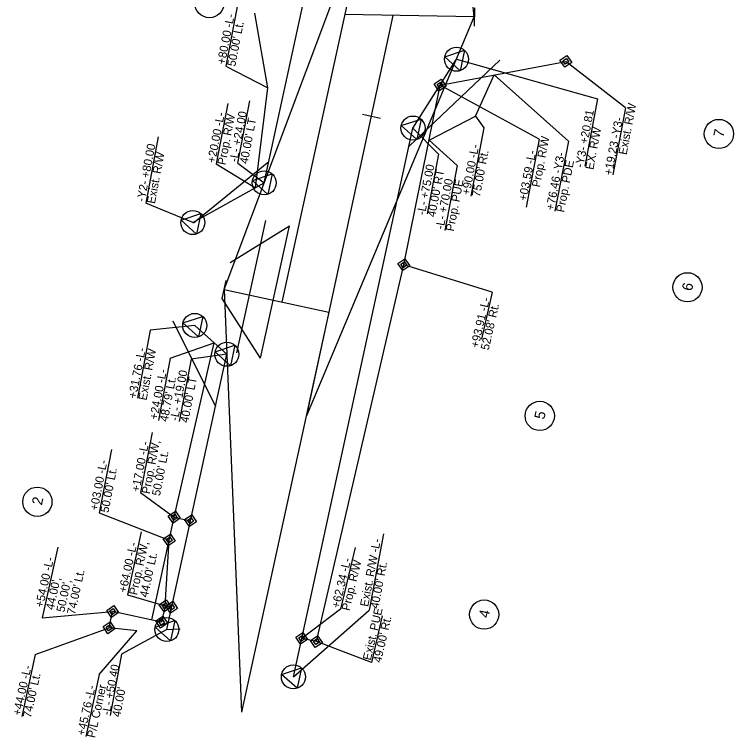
# Model space of a CAD drawing. Extents: x 1610947 to 1617684, y 899814 to 904658.
# Drawn here: x 1616111.3 to 1616541.5, y 899813.7 to 900246.6 of the extents above; entities that cross this region are included whole.
import ezdxf

# ---------------------------------------------------------------- set-up
doc = ezdxf.new("R2010")
doc.units = 0
for name, color, linetype in [('Prop Conc 1ft 6in Curb and Gutter', 7, 'Continuous'), ('Prop Conc Valley Gutter', 7, 'Continuous'), ('Prop EOT Dash', 7, 'Continuous'), ('Prop Hatching', 7, 'Continuous'), ('Prop Horizontal Alignment Direction Label', 7, 'Continuous'), ('Prop Horizontal Alignment Tick Label', 7, 'Continuous'), ('Prop ROW Marker CELL', 7, 'Continuous'), ('Prop ROW RW Lines', 7, 'Continuous'), ('Prop ROW Station Offsets', 7, 'Continuous'), ('Scratch_Level_2', 7, 'Continuous'), ('Scratch_Level_3', 7, 'Continuous'), ('Scratch_Level_8', 7, 'Continuous'), ('Typical Terminator CELL', 7, 'Continuous')]:
    doc.layers.add(name, color=color, linetype=linetype)

msp = doc.modelspace()

# ---------------------------------------------------------------- linework, layer by layer
at = {"layer": 'Prop Conc 1ft 6in Curb and Gutter'}
for p, q in [((1616244.83, 900252.28), (1616237.75, 900215.63)), ((1616237.75, 900215.63), (1616262.86, 900202.61)), ((1616238.96, 900193.29), (1616232, 900157.23)), ((1616387.13, 900185.77), (1616392.22, 900178.8)), ((1616392.22, 900178.8), (1616384.45, 900137.85)), ((1616359.33, 900171.36), (1616376.19, 900156.16)), ((1616442.71, 900170.81), (1616434.62, 900128.9)), ((1616232, 900157.23), (1616255.43, 900142.82)), ((1616376.19, 900156.16), (1616368.8, 900117.25))]:
    msp.add_line(p, q, dxfattribs=at)
msp.add_lwpolyline([(1616442.71, 900170.81), (1616398.24, 900210.39)], dxfattribs=at)
at = {"layer": 'Prop Conc Valley Gutter'}
for p, q in [((1616347.37, 900167.7), (1616401.7, 900219.28)), ((1616218.41, 900121.92), (1616263.49, 900158.5)), ((1616206.14, 900063.18), (1616231.56, 900011.94))]:
    msp.add_line(p, q, dxfattribs=at)
at = {"layer": 'Prop EOT Dash'}
for points in [[(1616437.65, 900219.18), (1616441.86, 900222.05), (1616444.72, 900217.84), (1616440.51, 900214.98)], [(1616439.42, 900218.85), (1616441.52, 900220.28), (1616442.95, 900218.18), (1616440.85, 900216.74)], [(1616362.43, 900204.96), (1616366.64, 900207.83), (1616369.5, 900203.62), (1616365.3, 900200.75)], [(1616364.2, 900204.62), (1616366.3, 900206.06), (1616367.74, 900203.95), (1616365.63, 900202.52)], [(1616340.74, 900097.44), (1616344.95, 900100.31), (1616347.82, 900096.1), (1616343.61, 900093.23)], [(1616342.51, 900097.11), (1616344.61, 900098.54), (1616346.05, 900096.43), (1616343.94, 900095)], [(1616203.34, 899946.31), (1616207.55, 899949.18), (1616210.42, 899944.97), (1616206.21, 899942.1)], [(1616205.11, 899945.97), (1616207.22, 899947.41), (1616208.65, 899945.3), (1616206.55, 899943.87)], [(1616213.12, 899944.18), (1616217.32, 899947.05), (1616220.19, 899942.84), (1616215.98, 899939.97)], [(1616214.88, 899943.85), (1616216.99, 899945.28), (1616218.42, 899943.17), (1616216.32, 899941.74)], [(1616200.36, 899932.63), (1616204.57, 899935.5), (1616207.44, 899931.29), (1616203.23, 899928.42)], [(1616202.13, 899932.3), (1616204.24, 899933.73), (1616205.67, 899931.62), (1616203.57, 899930.19)], [(1616197.93, 899893.25), (1616202.13, 899896.11), (1616205, 899891.9), (1616200.79, 899889.04)], [(1616199.69, 899892.91), (1616201.8, 899894.34), (1616203.23, 899892.24), (1616201.13, 899890.81)], [(1616201.83, 899892.4), (1616206.04, 899895.26), (1616208.91, 899891.05), (1616204.7, 899888.19)], [(1616203.6, 899892.06), (1616205.71, 899893.49), (1616207.14, 899891.39), (1616205.03, 899889.96)], [(1616166.48, 899889.86), (1616170.69, 899892.73), (1616173.56, 899888.52), (1616169.35, 899885.65)], [(1616168.25, 899889.53), (1616170.36, 899890.96), (1616171.79, 899888.86), (1616169.69, 899887.42)], [(1616195.8, 899883.48), (1616200.01, 899886.34), (1616202.87, 899882.13), (1616198.66, 899879.27)], [(1616197.57, 899883.14), (1616199.67, 899884.57), (1616201.1, 899882.47), (1616199, 899881.04)], [(1616164.36, 899880.09), (1616168.56, 899882.96), (1616171.43, 899878.75), (1616167.22, 899875.88)], [(1616166.12, 899879.76), (1616168.23, 899881.19), (1616169.66, 899879.08), (1616167.56, 899877.65)], [(1616279.65, 899873.74), (1616283.85, 899876.61), (1616286.72, 899872.4), (1616282.51, 899869.53)], [(1616281.41, 899873.4), (1616283.52, 899874.84), (1616284.95, 899872.73), (1616282.85, 899871.3)], [(1616288.44, 899871.82), (1616292.65, 899874.69), (1616295.51, 899870.48), (1616291.3, 899867.62)], [(1616290.21, 899871.49), (1616292.31, 899872.92), (1616293.74, 899870.82), (1616291.64, 899869.38)]]:
    msp.add_lwpolyline(points, close=True, dxfattribs=at)
at = {"layer": 'Prop Hatching'}
for centre in [(1616227.92, 900253.37), (1616532.79, 900175.04), (1616513.98, 900083.25), (1616425.61, 900006.24), (1616124.98, 899954.88), (1616392.33, 899887.32)]:
    msp.add_circle(centre, 8.75, dxfattribs=at)
at = {"layer": 'Prop Horizontal Alignment Direction Label'}
for p, q in [((1616344.28, 900096.77), (1616365.97, 900204.29)), ((1616291.98, 899871.15), (1616344.28, 900096.77)), ((1616167.89, 899879.42), (1616170.02, 899889.19)), ((1616199.33, 899882.81), (1616170.02, 899889.19)), ((1616201.46, 899892.58), (1616199.33, 899882.81)), ((1616205.37, 899891.72), (1616201.46, 899892.58)), ((1616184.59, 899877.59), (1616167.89, 899879.42)), ((1616291.98, 899871.15), (1616283.18, 899873.07))]:
    msp.add_line(p, q, dxfattribs=at)
at = {"layer": 'Prop Horizontal Alignment Tick Label'}
for p, q in [((1616397.19, 900080.35), (1616344.28, 900096.77)), ((1616397.19, 900080.35), (1616390.74, 900052.27)), ((1616187.09, 899936.95), (1616178.86, 899899.23)), ((1616137.18, 899927.69), (1616127.93, 899885.32)), ((1616315.11, 899927.48), (1616306.31, 899890.59)), ((1616127.93, 899885.32), (1616170.02, 899889.19)), ((1616331.27, 899886.64), (1616324.82, 899858.57)), ((1616324.82, 899858.57), (1616291.98, 899871.15)), ((1616123.72, 899863.42), (1616115.63, 899826.37)), ((1616162.02, 899851.42), (1616153.94, 899814.38))]:
    msp.add_line(p, q, dxfattribs=at)
for points in [[(1616178.86, 899899.23), (1616201.46, 899892.58)], [(1616306.31, 899890.59), (1616283.18, 899873.07)], [(1616123.72, 899863.42), (1616167.89, 899879.42)], [(1616162.02, 899851.42), (1616184.59, 899877.59)]]:
    msp.add_lwpolyline(points, dxfattribs=at)
at = {"layer": 'Prop ROW Marker CELL'}
for p, q in [((1616375.75, 900219.79), (1616375.75, 900219.79)), ((1616441.18, 900218.51), (1616441.18, 900218.51)), ((1616365.97, 900204.29), (1616365.97, 900204.29)), ((1616349.74, 900178.57), (1616349.74, 900178.57)), ((1616260.71, 900145.77), (1616260.71, 900145.77)), ((1616218.01, 900122), (1616218.01, 900122)), ((1616344.28, 900096.77), (1616344.28, 900096.77)), ((1616219.16, 900060.42), (1616219.16, 900060.42)), ((1616238.36, 900043.17), (1616238.36, 900043.17)), ((1616206.88, 899945.64), (1616206.88, 899945.64)), ((1616216.65, 899943.51), (1616216.65, 899943.51)), ((1616203.9, 899931.96), (1616203.9, 899931.96)), ((1616170.02, 899889.19), (1616170.02, 899889.19)), ((1616201.46, 899892.58), (1616201.46, 899892.58)), ((1616205.37, 899891.72), (1616205.37, 899891.72)), ((1616199.33, 899882.81), (1616199.33, 899882.81)), ((1616167.89, 899879.42), (1616167.89, 899879.42)), ((1616202.46, 899878.37), (1616202.46, 899878.37)), ((1616283.18, 899873.07), (1616283.18, 899873.07)), ((1616291.98, 899871.15), (1616291.98, 899871.15)), ((1616278.17, 899850.04), (1616278.17, 899850.04))]:
    msp.add_line(p, q, dxfattribs=at)
for points in [[(1616377.97, 900212.92), (1616368.7, 900221.28), (1616380.57, 900225.15)], [(1616351.96, 900171.71), (1616342.69, 900180.06), (1616354.56, 900183.93)], [(1616262.94, 900138.9), (1616253.67, 900147.26), (1616265.53, 900151.13)], [(1616220.23, 900115.14), (1616210.96, 900123.5), (1616222.83, 900127.37)], [(1616221.39, 900053.56), (1616212.12, 900061.91), (1616223.98, 900065.78)], [(1616240.59, 900036.31), (1616231.32, 900044.67), (1616243.18, 900048.54)], [(1616204.68, 899871.51), (1616195.42, 899879.87), (1616207.28, 899883.74)], [(1616280.39, 899843.18), (1616271.12, 899851.54), (1616282.99, 899855.41)]]:
    msp.add_lwpolyline(points, close=True, dxfattribs=at)
for centre in [(1616375.75, 900219.79), (1616349.74, 900178.57), (1616260.71, 900145.77), (1616218.01, 900122), (1616219.16, 900060.42), (1616238.36, 900043.17), (1616202.46, 899878.37), (1616278.17, 899850.04)]:
    msp.add_circle(centre, 7.2, dxfattribs=at)
at = {"layer": 'Prop ROW RW Lines'}
for p, q in [((1616260.71, 900145.77), (1616369.28, 900644.08)), ((1616349.74, 900178.57), (1616375.75, 900219.79)), ((1616278.17, 899850.04), (1616349.74, 900178.57)), ((1616218.01, 900122), (1616260.71, 900145.77)), ((1616238.36, 900043.17), (1616219.16, 900060.42)), ((1616202.46, 899878.37), (1616238.36, 900043.17)), ((1616202.46, 899878.37), (1616210.42, 899878.72))]:
    msp.add_line(p, q, dxfattribs=at)
at = {"layer": 'Prop ROW Station Offsets'}
for p, q in [((1616375.75, 900219.79), (1616460.13, 900196.06)), ((1616460.13, 900196.06), (1616452.47, 900155.71)), ((1616349.74, 900178.57), (1616365.01, 900162.99)), ((1616197.33, 900173.25), (1616189.82, 900133.68)), ((1616365.01, 900162.99), (1616358.21, 900127.17)), ((1616244.95, 900157.47), (1616260.71, 900145.77)), ((1616218.01, 900122), (1616189.82, 900133.68)), ((1616192.55, 900057.65), (1616184.81, 900016.87)), ((1616219.16, 900060.42), (1616192.55, 900057.65)), ((1616216.93, 900040.17), (1616209.77, 900002.82)), ((1616238.36, 900043.17), (1616216.93, 900040.17)), ((1616332.17, 899935.73), (1616323.5, 899890.03)), ((1616278.17, 899850.04), (1616323.5, 899890.03)), ((1616202.46, 899878.37), (1616175.42, 899863.63)), ((1616175.42, 899863.63), (1616168.46, 899826.99))]:
    msp.add_line(p, q, dxfattribs=at)
msp.add_lwpolyline([(1616244.95, 900157.47), (1616252.06, 900194.9)], dxfattribs=at)
at = {"layer": 'Scratch_Level_2'}
for p, q in [((1616386.37, 900245.08), (1616361.19, 900485.97)), ((1616236.81, 900081.92), (1616323.66, 900313.74)), ((1616271.51, 900074.36), (1616323.66, 900313.74)), ((1616386.47, 900250.58), (1616386.26, 900239.59)), ((1616286.24, 900006.55), (1616337.97, 900246.03)), ((1616286.24, 900006.55), (1616386.37, 900245.08)), ((1616386.37, 900245.08), (1616309.03, 900246.59)), ((1616319.55, 900186.82), (1616330.3, 900184.48)), ((1616244.41, 900043.93), (1616261.66, 900123.16)), ((1616240.35, 900098.03), (1616275.83, 900120.07)), ((1616258.58, 900040.84), (1616275.83, 900120.07)), ((1616235.64, 900076.54), (1616237.98, 900087.29)), ((1616236.81, 900081.92), (1616299.36, 900068.29)), ((1616236.81, 900081.92), (1616247.21, 899828.91)), ((1616258.58, 900040.84), (1616235.64, 900076.54)), ((1616299.36, 900068.29), (1616247.21, 899828.91))]:
    msp.add_line(p, q, dxfattribs=at)
at = {"layer": 'Scratch_Level_3'}
for p, q in [((1616262.86, 900202.61), (1616255.19, 900247.27)), ((1616387.13, 900185.77), (1616398.24, 900210.39)), ((1616255.43, 900142.82), (1616262.86, 900202.61)), ((1616359.33, 900171.36), (1616387.13, 900185.77)), ((1616206.88, 899945.64), (1616230.84, 900049.93)), ((1616204.52, 900040.78), (1616197.44, 900003.53)), ((1616193.47, 899884.08), (1616203.9, 899931.96)), ((1616291.2, 899909.87), (1616291.2, 899909.87))]:
    msp.add_line(p, q, dxfattribs=at)
msp.add_lwpolyline([(1616204.52, 900040.78), (1616230.84, 900049.93)], dxfattribs=at)
at = {"layer": 'Scratch_Level_8'}
for p, q in [((1616476.95, 900190.66), (1616441.18, 900218.51)), ((1616476.95, 900190.66), (1616469.34, 900150.54)), ((1616425.18, 900171.88), (1616417.46, 900131.2)), ((1616193.63, 899996.37), (1616186.67, 899960.32)), ((1616169.31, 899986.19), (1616162.01, 899948.33)), ((1616162.01, 899948.33), (1616203.9, 899931.96))]:
    msp.add_line(p, q, dxfattribs=at)
for points in [[(1616425.18, 900171.88), (1616365.97, 900204.29)], [(1616186.67, 899960.32), (1616206.88, 899945.64)]]:
    msp.add_lwpolyline(points, dxfattribs=at)
at = {"layer": 'Typical Terminator CELL'}
for p, q in [((1616365.97, 900204.29), (1616441.18, 900218.51)), ((1616203.9, 899931.96), (1616206.88, 899945.64)), ((1616206.88, 899945.64), (1616216.65, 899943.51)), ((1616201.46, 899892.58), (1616203.9, 899931.96))]:
    msp.add_line(p, q, dxfattribs=at)

# ---------------------------------------------------------------- texts
at = {"layer": 'Prop Conc 1ft 6in Curb and Gutter'}
for s, rotation, p in [('+80.00 -L-', 79.0727, (1616237.25, 900216.35)), ("50.00' Lt.", 79.0727, (1616243.39, 900215.16)), ('+20.00 -L-', 79.0727, (1616231.39, 900157.35)), ('Prop. R/W', 79.0727, (1616237.52, 900156.17)), ('+90.00 -L-', 79.2494, (1616383.66, 900138.22)), ("75.00' Rt.", 79.2494, (1616389.8, 900137.05)), ('+76.46 -Y3-', 79.0727, (1616434.01, 900129.02)), ('Prop. PDE', 79.0727, (1616440.14, 900127.84)), ('-L- +70.00', 79.2494, (1616368.01, 900117.62)), ('Prop. PUE', 79.2494, (1616374.15, 900116.45))]:
    msp.add_text(s, height=5, rotation=rotation, dxfattribs=at).set_placement(p)
at = {"layer": 'Prop Hatching'}
for s, p in [('7', (1616535.46, 900172.64)), ('6', (1616516.62, 900080.71)), ('5', (1616428.29, 900003.84)), ('2', (1616127.66, 899952.49)), ('4', (1616395.01, 899884.93))]:
    msp.add_text(s, height=6.25, rotation=77.7167, dxfattribs=at).set_placement(p)
at = {"layer": 'Prop Horizontal Alignment Tick Label'}
for s, rotation, p in [('+93.91 -L-', 77.0556, (1616388.93, 900046.7)), ("52.08' Rt.", 77.0556, (1616395.02, 900045.3)), ('+64.00 -L-', 77.6862, (1616178.27, 899900.07)), ('Prop. R/W,', 77.6862, (1616184.62, 899898.68)), ("44.00' Lt.", 77.6862, (1616190.98, 899897.29)), ('+54.00 -L-', 77.6862, (1616128.41, 899891.21)), ('+62.34 -L-', 76.5863, (1616305.7, 899890.74)), ('Prop. R/W', 76.5863, (1616311.78, 899889.29)), ("74.00' Lt.", 77.6862, (1616147.46, 899887.05)), ("44.00',", 77.6862, (1616134.76, 899889.82)), ("50.00',", 77.6862, (1616141.11, 899888.43)), ('Exist. PUE', 77.0556, (1616324.49, 899859.62)), ("49.00' Rt.", 77.0556, (1616330.58, 899858.22)), ('+44.00 -L-', 77.6862, (1616115.02, 899826.51)), ("74.00' Lt.", 77.6862, (1616121.13, 899825.17)), ('P/L Corner', 77.6862, (1616159.43, 899813.18)), ('+45.76 -L-', 77.6862, (1616153.33, 899814.51))]:
    msp.add_text(s, height=5, rotation=rotation, dxfattribs=at).set_placement(p)
at = {"layer": 'Prop ROW Station Offsets'}
for s, p in [('-L- +24.00', (1616244.69, 900158.02)), ('-Y3- +20.81', (1616451.5, 900154.54)), ("40.00' LT", (1616250.83, 900156.86)), ('EX. R/W', (1616457.64, 900153.38)), ('-Y2- +80.00', (1616189.17, 900134.16)), ('Exist. R/W', (1616195.31, 900133)), ('-L- +75.00', (1616356.92, 900126.19)), ("40.00' RT", (1616363.06, 900125.03)), ('+31.76 -L-', (1616184.15, 900016.45)), ('Exist. R/W', (1616190.29, 900015.28)), ('-L- +19.00', (1616209.12, 900003.03)), ("40.00' LT", (1616215.27, 900001.86)), ('Exist. R/W -L-', (1616322.89, 899891.75)), ("40.00' Rt.", (1616329.03, 899890.58)), ('-L- +50.40', (1616168.39, 899826.83)), ("40.00'", (1616174.53, 899825.67))]:
    msp.add_text(s, height=5, rotation=79.2494, dxfattribs=at).set_placement(p)
at = {"layer": 'Scratch_Level_3'}
for s, p in [('+24.00 -L-', (1616196.83, 900003.65)), ("48.79' Lt.", (1616202.97, 900002.48))]:
    msp.add_text(s, height=5, rotation=79.2494, dxfattribs=at).set_placement(p)
at = {"layer": 'Scratch_Level_8'}
for s, rotation, p in [('Exist. R/W', 79.2494, (1616477.54, 900162.26)), ('+19.23 -Y3-', 79.2494, (1616468.85, 900149.98)), ('Prop. R/W', 79.2494, (1616425.65, 900142.87)), ('+03.59 -L-', 79.2494, (1616417.74, 900134.69)), ('+17.00 -L-', 79.0727, (1616186.06, 899960.44)), ('Prop. R/W,', 79.0727, (1616192.19, 899959.25)), ("50.00' Lt.", 79.0727, (1616198.33, 899958.07)), ('+03.00 -L-', 79.0727, (1616161.14, 899949.25)), ("50.00' Lt.", 79.0727, (1616167.52, 899948.02))]:
    msp.add_text(s, height=5, rotation=rotation, dxfattribs=at).set_placement(p)

doc.saveas('drawing.dxf')
